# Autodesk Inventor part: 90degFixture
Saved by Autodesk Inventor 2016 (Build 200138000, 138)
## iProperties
Created: 2015-11
Part Number: 90degFixture
Material: Generic
Document SubType Name: Modeling
Designer: John
Density: 1 g/cm^3
Appearance: Default
Author: John
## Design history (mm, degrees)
feature "Base1"
body "Solid1"
